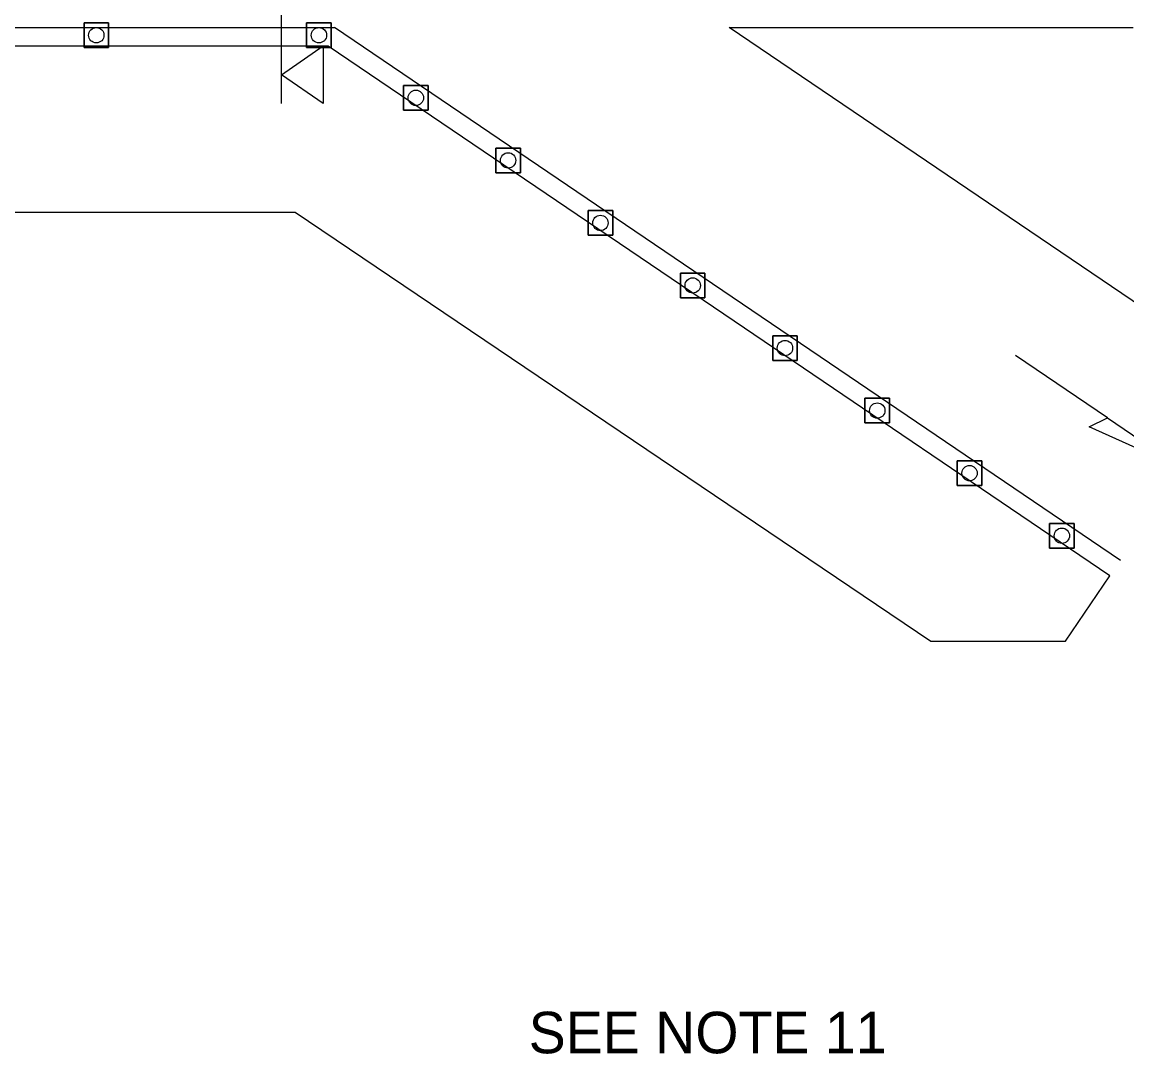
# Model space of a CAD drawing. Extents: x 99999.1 to 100055.7, y 99995 to 100013.2.
# Drawn here: x 100022.17 to 100024.086, y 100005.332 to 100007.12 of the extents above; entities that cross this region are included whole.
import ezdxf

# ---------------------------------------------------------------- set-up
doc = ezdxf.new("R2010")
doc.units = 0
for name, color, linetype in [('RD_MK_LineEdgeYellow', 7, 'Continuous'), ('TR_SN_ConstructionSigns', 7, 'Continuous'), ('TR_WZ_PortableSignMountBlk-Org', 7, 'Continuous'), ('TR_WZ_TrafficCone', 7, 'Continuous'), ('TR_WZ_WorkZoneDetails', 7, 'Continuous')]:
    doc.layers.add(name, color=color, linetype=linetype)

msp = doc.modelspace()

# ---------------------------------------------------------------- linework, layer by layer
at = {"layer": 'RD_MK_LineEdgeYellow'}
for p, q in [((100020.32, 100007.1109), (100022.7119, 100007.1109)), ((100024.0746, 100006.1873), (100022.7119, 100007.1109)), ((100024.29, 100006.5052), (100024.0249, 100006.6849))]:
    msp.add_line(p, q, dxfattribs=at)
at = {"layer": 'TR_WZ_PortableSignMountBlk-Org'}
msp.add_line((100022.6202, 100006.979), (100022.6202, 100007.079), dxfattribs=at)
msp.add_lwpolyline([(100022.6202, 100007.0289), (100022.6921, 100007.079), (100022.6921, 100006.979)], close=True, dxfattribs=at)
at = {"layer": 'TR_WZ_TrafficCone'}
for points in [[(100022.2776, 100007.1189), (100022.3203, 100007.1189), (100022.3203, 100007.0762), (100022.2776, 100007.0762), (100022.2776, 100007.1189)], [(100022.2776, 100007.0762), (100022.3203, 100007.0762), (100022.3203, 100007.1189), (100022.2776, 100007.1189), (100022.2776, 100007.0762)], [(100022.6635, 100007.1189), (100022.7062, 100007.1189), (100022.7062, 100007.0762), (100022.6635, 100007.0762), (100022.6635, 100007.1189)], [(100022.6635, 100007.0762), (100022.7062, 100007.0762), (100022.7062, 100007.1189), (100022.6635, 100007.1189), (100022.6635, 100007.0762)], [(100022.8316, 100007.0105), (100022.8742, 100007.0105), (100022.8742, 100006.9678), (100022.8316, 100006.9678), (100022.8316, 100007.0105)], [(100022.8316, 100006.9678), (100022.8742, 100006.9678), (100022.8742, 100007.0105), (100022.8316, 100007.0105), (100022.8316, 100006.9678)], [(100022.9916, 100006.902), (100023.0342, 100006.902), (100023.0342, 100006.8593), (100022.9916, 100006.8593), (100022.9916, 100006.902)], [(100022.9916, 100006.8593), (100023.0342, 100006.8593), (100023.0342, 100006.902), (100022.9916, 100006.902), (100022.9916, 100006.8593)], [(100023.1516, 100006.7936), (100023.1942, 100006.7936), (100023.1942, 100006.7509), (100023.1516, 100006.7509), (100023.1516, 100006.7936)], [(100023.1516, 100006.7509), (100023.1942, 100006.7509), (100023.1942, 100006.7936), (100023.1516, 100006.7936), (100023.1516, 100006.7509)], [(100023.3116, 100006.6851), (100023.3542, 100006.6851), (100023.3542, 100006.6424), (100023.3116, 100006.6424), (100023.3116, 100006.6851)], [(100023.3116, 100006.6424), (100023.3542, 100006.6424), (100023.3542, 100006.6851), (100023.3116, 100006.6851), (100023.3116, 100006.6424)], [(100023.4716, 100006.5767), (100023.5142, 100006.5767), (100023.5142, 100006.534), (100023.4716, 100006.534), (100023.4716, 100006.5767)], [(100023.4716, 100006.534), (100023.5142, 100006.534), (100023.5142, 100006.5767), (100023.4716, 100006.5767), (100023.4716, 100006.534)], [(100023.6316, 100006.4682), (100023.6742, 100006.4682), (100023.6742, 100006.4255), (100023.6316, 100006.4255), (100023.6316, 100006.4682)], [(100023.6316, 100006.4255), (100023.6742, 100006.4255), (100023.6742, 100006.4682), (100023.6316, 100006.4682), (100023.6316, 100006.4255)], [(100023.7916, 100006.3598), (100023.8342, 100006.3598), (100023.8342, 100006.3171), (100023.7916, 100006.3171), (100023.7916, 100006.3598)], [(100023.7916, 100006.3171), (100023.8342, 100006.3171), (100023.8342, 100006.3598), (100023.7916, 100006.3598), (100023.7916, 100006.3171)], [(100023.9516, 100006.2513), (100023.9942, 100006.2513), (100023.9942, 100006.2086), (100023.9516, 100006.2086), (100023.9516, 100006.2513)], [(100023.9516, 100006.2086), (100023.9942, 100006.2086), (100023.9942, 100006.2513), (100023.9516, 100006.2513), (100023.9516, 100006.2086)]]:
    msp.add_lwpolyline(points, dxfattribs=at)
for centre in [(100022.2989, 100007.0976), (100022.6849, 100007.0976), (100022.8529, 100006.9891), (100023.0129, 100006.8807), (100023.1729, 100006.7722), (100023.3329, 100006.6638), (100023.4929, 100006.5553), (100023.6529, 100006.4469), (100023.8129, 100006.3384), (100023.9729, 100006.23)]:
    msp.add_circle(centre, 0.0133, dxfattribs=at)
at = {"layer": 'TR_WZ_WorkZoneDetails'}
for p, q in [((100022.6202, 100007.0789), (100022.6202, 100008.2789)), ((100024.0249, 100006.6849), (100023.3963, 100007.1109)), ((100023.3963, 100007.1109), (100024.0968, 100007.1109)), ((100020.32, 100006.7909), (100022.6438, 100006.7909)), ((100022.6438, 100006.7909), (100023.746, 100006.047)), ((100024.0522, 100006.4344), (100023.8925, 100006.5427))]:
    msp.add_line(p, q, dxfattribs=at)
for points in [[(100020.4, 100006.7909), (100022.6438, 100006.7909), (100023.746, 100006.047), (100023.9795, 100006.047), (100024.0562, 100006.1602), (100023.4045, 100006.602), (100022.9878, 100006.8844), (100022.7008, 100007.0789), (100020.4, 100007.0789)], [(100024.1823, 100006.3462), (100024.0201, 100006.4189), (100024.0522, 100006.4344)]]:
    msp.add_lwpolyline(points, close=True, dxfattribs=at)

# ---------------------------------------------------------------- texts
at = {"layer": 'TR_SN_ConstructionSigns'}
msp.add_text('SEE NOTE 11', height=0.072, rotation=360, dxfattribs=at).set_placement((100023.0485, 100005.3327))

doc.saveas('drawing.dxf')
